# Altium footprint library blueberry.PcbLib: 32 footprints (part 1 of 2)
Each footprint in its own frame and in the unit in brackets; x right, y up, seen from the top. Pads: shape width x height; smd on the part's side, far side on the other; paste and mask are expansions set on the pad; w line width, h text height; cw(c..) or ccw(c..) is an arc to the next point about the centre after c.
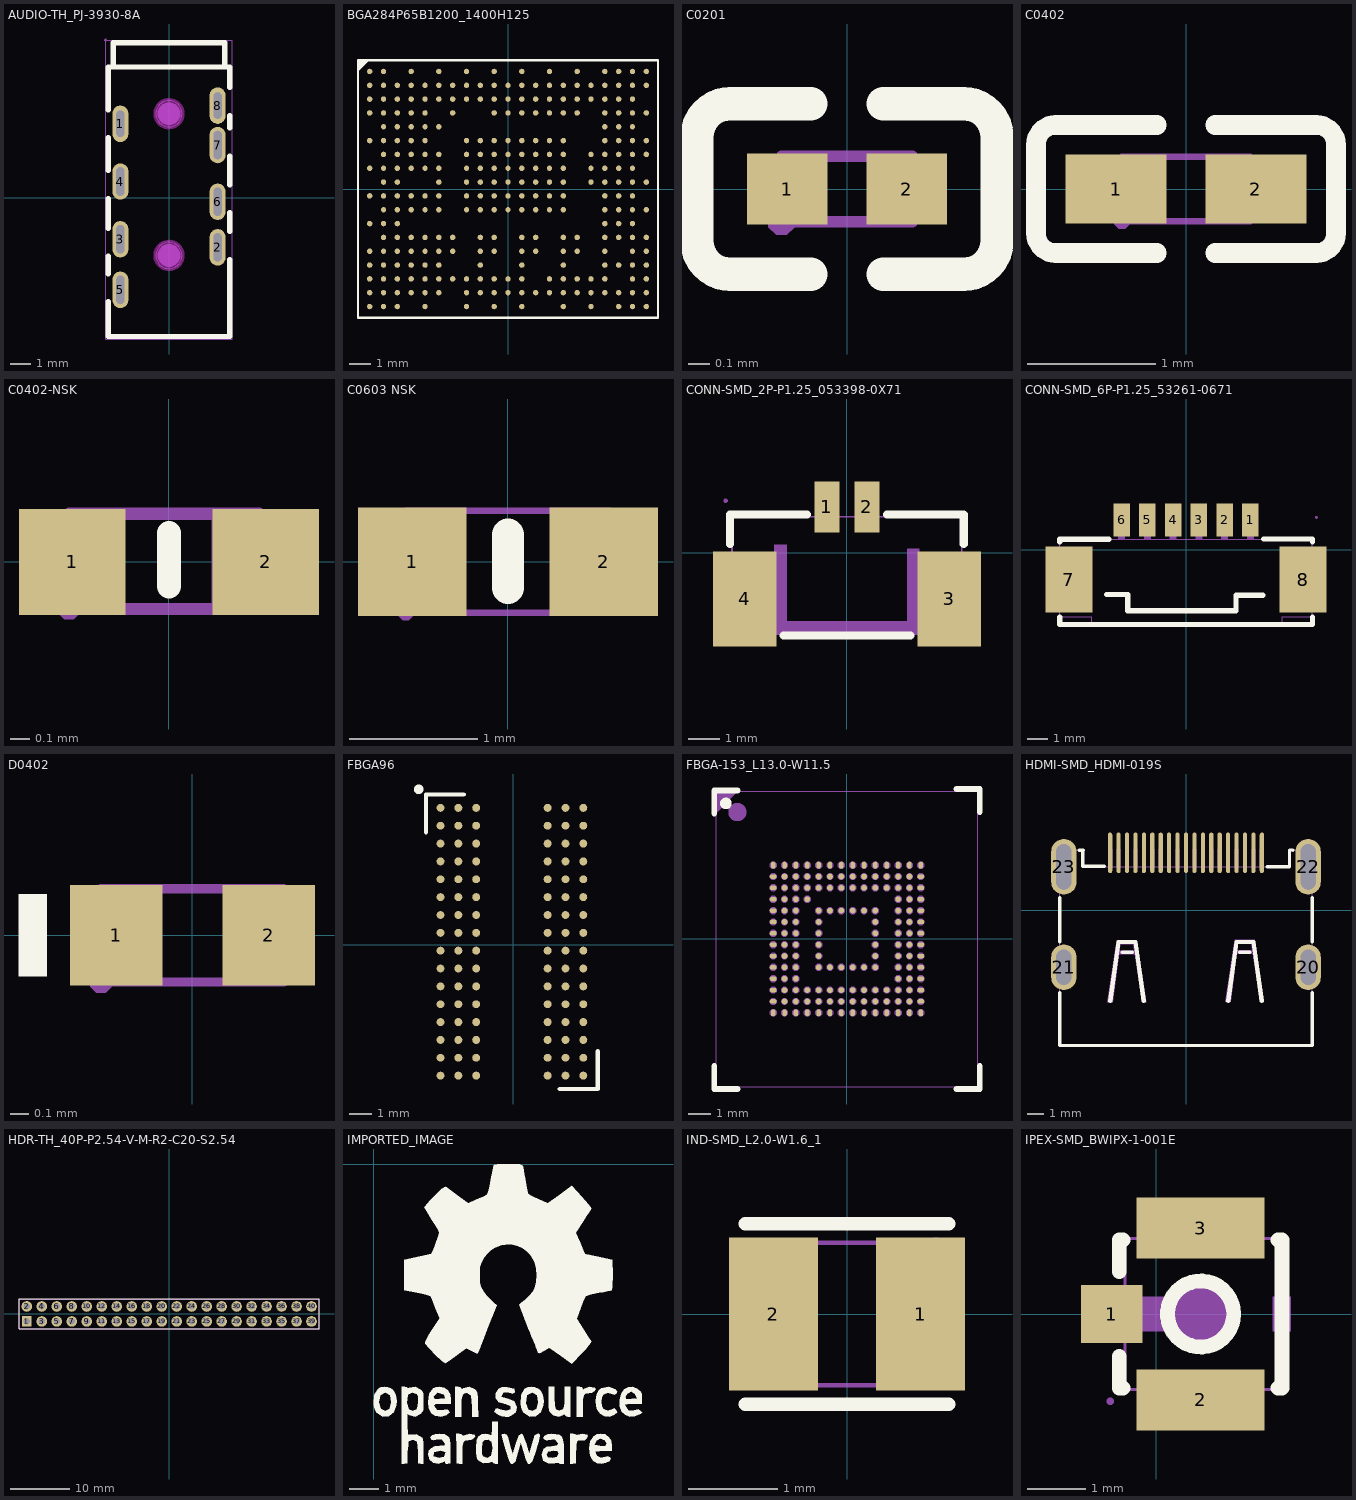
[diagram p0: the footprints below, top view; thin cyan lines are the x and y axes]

## AUDIO-TH_PJ-3930-8A [mil]
pads (8):
  oval 31.5x70.9 hole 15.7 slot 51.2 at 90 deg paste-99999 mask+2: 1(-94.5,143.7) 8(94.5,179.1)
  oval 31.5x70.9 hole 15.7 slot 55.1 at 90 deg paste-99999 mask+2: 2(94.5,-96.5) 3(-94.5,-80.7) 4(-94.5,31.5) 5(-94.5,-179.1) 6(94.5,-7.9) 7(94.5,102.4)
Top Overlay:
  lines w10: -118.1,-202.4 -118.1,-269.7 118.1,-269.7 118.1,-119.8 ; -118.1,-148 -118.1,-113.9 ; -118.1,-59.5 -118.1,-1.6 ; -118.1,52.8 -118.1,116.5 ; -118.1,170.9 -118.1,253.9 90,253.9 118.1,253.9 118.1,214.2 ; -108.3,253.9 -108.3,301.2 108.3,301.2 108.3,253.9 ; 118.1,-65.4 118.1,-29.2 ; 118.1,25.2 118.1,81 ; 118.1,135.4 118.1,159.8
Keep-Out Layer:
  board cut-out: -25.6,-112.2 -25.6,-115.57 -23.86,-122.08 -20.49,-127.92 -15.72,-132.69 -9.88,-136.06 -3.37,-137.8 3.37,-137.8 9.88,-136.06 15.72,-132.69 20.48,-127.92 23.86,-122.08 25.6,-115.57 25.6,-112.2 25.6,-108.83 23.86,-102.32 20.48,-96.48 15.72,-91.72 9.88,-88.34 3.37,-86.6 -3.37,-86.6 -9.88,-88.34 -15.72,-91.72 -20.49,-96.48 -23.86,-102.32 -25.6,-108.83
  board cut-out: -25.6,163.3 -25.6,159.93 -23.86,153.42 -20.49,147.58 -15.72,142.81 -9.88,139.44 -3.37,137.7 3.37,137.7 9.88,139.44 15.72,142.81 20.48,147.58 23.86,153.42 25.6,159.93 25.6,163.3 25.6,166.67 23.86,173.18 20.48,179.02 15.72,183.78 9.88,187.16 3.37,188.9 -3.37,188.9 -9.88,187.16 -15.72,183.78 -20.49,179.02 -23.86,173.18 -25.6,166.67
Keep-Out Layer:
  circle w10: c0,-112.2 r25.6
  circle w0.2: c0,-112.2 r25.6
  circle w10: c0,163.3 r25.6
  circle w0.2: c0,163.3 r25.6
Mechanical 1:
  circle w0.2: c0,-112.2 r25.6
  circle w0.2: c0,163.3 r25.6
Mechanical 15:
  region: 88.2,161.4 88.2,196.8 100.8,196.8 100.8,161.4
  region: 88.2,82.7 88.2,122.1 100.8,122.1 100.8,82.7
  region: 88.2,-27.6 88.2,11.8 100.8,11.8 100.8,-27.6
  region: -100.8,-198.9 -100.8,-159.5 -88.2,-159.5 -88.2,-198.9
  region: -100.8,11.8 -100.8,51.1 -88.2,51.1 -88.2,11.8
  region: -100.8,-100.3 -100.8,-61 -88.2,-61 -88.2,-100.3
  region: 88.2,-116.1 88.2,-76.7 100.8,-76.7 100.8,-116.1
  region: -100.8,126 -100.8,161.4 -88.2,161.4 -88.2,126
  region: -125.5,306.2 -125.5,305.21 -124.09,303.8 -122.11,303.8 -120.7,305.21 -120.7,306.2 -120.7,307.19 -122.11,308.6 -124.09,308.6 -125.5,307.19 -125.5,306.2
  region: -21.7,-112.2 -21.7,-116.52 -18.4,-124.49 -12.29,-130.6 -4.32,-133.9 4.32,-133.9 12.29,-130.6 18.4,-124.49 21.7,-116.52 21.7,-112.2 21.7,-107.88 18.4,-99.91 12.29,-93.8 4.32,-90.5 -4.32,-90.5 -12.29,-93.8 -18.4,-99.91 -21.7,-107.88 -21.7,-112.2
  region: -21.7,163.3 -21.7,158.98 -18.4,151.01 -12.29,144.9 -4.32,141.6 4.32,141.6 12.29,144.9 18.4,151.01 21.7,158.98 21.7,163.3 21.7,167.62 18.4,175.59 12.29,181.7 4.32,185 -4.32,185 -12.29,181.7 -18.4,175.59 -21.7,167.62 -21.7,163.3
  lines w2: -123.1,-274.7 -123.1,306.2 123.1,306.2 123.1,-274.7 -123.1,-274.7
3D body "13lB-AUDIO1-AUDIO-TH_PJ-3930-8A.step": height 214.55, standoff -118.1, extent -118.49,-275.55 118.1,303.15

## BGA284P65B1200_1400H125 [mil]
pads (284):
  round 10 smd paste+0.98 mask+1.97: A1(-255.91,217.52) A2(-230.31,217.52) A4(-179.13,217.52) A6(-127.95,217.52) A8(-76.77,217.52) A10(-25.59,217.52) A12(25.59,217.52) A14(76.77,217.52) A16(127.95,217.52) A18(179.13,217.52) A19(204.72,217.52) A20(230.31,217.52) A21(255.91,217.52) B1(-255.91,191.93) B2(-230.31,191.93) B3(-204.72,191.93) B4(-179.13,191.93) B5(-153.54,191.93) B6(-127.95,191.93) B7(-102.36,191.93) B8(-76.77,191.93) B9(-51.18,191.93) B10(-25.59,191.93) B11(0,191.93) B12(25.59,191.93) B13(51.18,191.93) B14(76.77,191.93) B15(102.36,191.93) B16(127.95,191.93) B17(153.54,191.93) B18(179.13,191.93) B19(204.72,191.93) B20(230.31,191.93) B21(255.91,191.93) C1(-255.91,166.34) C2(-230.31,166.34) C3(-204.72,166.34) C4(-179.13,166.34) C5(-153.54,166.34) C6(-127.95,166.34) C7(-102.36,166.34) C8(-76.77,166.34) C9(-51.18,166.34) C10(-25.59,166.34) C11(0,166.34) C12(25.59,166.34) C13(51.18,166.34) C14(76.77,166.34) C15(102.36,166.34) C16(127.95,166.34) C17(153.54,166.34) C18(179.13,166.34) C19(204.72,166.34) C20(230.31,166.34) D1(-255.91,140.75) D2(-230.31,140.75) D3(-204.72,140.75) D4(-179.13,140.75) D5(-153.54,140.75) D7(-102.36,140.75) D10(-25.59,140.75) D11(0,140.75) D12(25.59,140.75) D13(51.18,140.75) D14(76.77,140.75) D15(102.36,140.75) D16(127.95,140.75) D18(179.13,140.75) D19(204.72,140.75) D20(230.31,140.75) D21(255.91,140.75) E2(-230.31,115.16) E3(-204.72,115.16) E4(-179.13,115.16) E5(-153.54,115.16) E6(-127.95,115.16) E18(179.13,115.16) E19(204.72,115.16) E20(230.31,115.16) F1(-255.91,89.57) F2(-230.31,89.57) F3(-204.72,89.57) F4(-179.13,89.57) F5(-153.54,89.57) F8(-76.77,89.57) F9(-51.18,89.57) F10(-25.59,89.57) F11(0,89.57) F12(25.59,89.57) F13(51.18,89.57) F14(76.77,89.57) F15(102.36,89.57) F18(179.13,89.57) F19(204.72,89.57) F20(230.31,89.57) F21(255.91,89.57) G2(-230.31,63.98) G3(-204.72,63.98) G4(-179.13,63.98) G5(-153.54,63.98) G6(-127.95,63.98) G8(-76.77,63.98) G9(-51.18,63.98) G10(-25.59,63.98) G11(0,63.98) G12(25.59,63.98) G13(51.18,63.98) G14(76.77,63.98) G15(102.36,63.98) G17(153.54,63.98) G18(179.13,63.98) G19(204.72,63.98) G20(230.31,63.98) G21(255.91,63.98) H1(-255.91,38.39) H2(-230.31,38.39) H3(-204.72,38.39) H4(-179.13,38.39) H5(-153.54,38.39) H6(-127.95,38.39) H8(-76.77,38.39) H9(-51.18,38.39) H10(-25.59,38.39) H11(0,38.39) H12(25.59,38.39) H13(51.18,38.39) H14(76.77,38.39) H15(102.36,38.39) H17(153.54,38.39) H18(179.13,38.39) H19(204.72,38.39) H20(230.31,38.39) J2(-230.31,12.8) J3(-204.72,12.8) J6(-127.95,12.8) J8(-76.77,12.8) J9(-51.18,12.8) J10(-25.59,12.8) J11(0,12.8) J12(25.59,12.8) J13(51.18,12.8) J14(76.77,12.8) J15(102.36,12.8) J17(153.54,12.8) J18(179.13,12.8) J19(204.72,12.8) J20(230.31,12.8) J21(255.91,12.8) K1(-255.91,-12.8) K2(-230.31,-12.8) K3(-204.72,-12.8) K4(-179.13,-12.8) K5(-153.54,-12.8) K6(-127.95,-12.8) K8(-76.77,-12.8) K9(-51.18,-12.8) K10(-25.59,-12.8) K11(0,-12.8) K12(25.59,-12.8) K13(51.18,-12.8) K14(76.77,-12.8) K15(102.36,-12.8) K18(179.13,-12.8) K19(204.72,-12.8) K20(230.31,-12.8) L2(-230.31,-38.39) L3(-204.72,-38.39) L4(-179.13,-38.39) L5(-153.54,-38.39) L6(-127.95,-38.39) L8(-76.77,-38.39) L9(-51.18,-38.39) L10(-25.59,-38.39) L11(0,-38.39) L12(25.59,-38.39) L13(51.18,-38.39) L14(76.77,-38.39) L15(102.36,-38.39) L18(179.13,-38.39) L19(204.72,-38.39) L20(230.31,-38.39) L21(255.91,-38.39) M1(-255.91,-63.98) M2(-230.31,-63.98) M3(-204.72,-63.98) M18(179.13,-63.98) M19(204.72,-63.98) M20(230.31,-63.98) N2(-230.31,-89.57) N3(-204.72,-89.57) N4(-179.13,-89.57) N5(-153.54,-89.57) N6(-127.95,-89.57) N7(-102.36,-89.57) N9(-51.18,-89.57) N10(-25.59,-89.57) N12(25.59,-89.57) N13(51.18,-89.57) N15(102.36,-89.57) N16(127.95,-89.57) N18(179.13,-89.57) N19(204.72,-89.57) N20(230.31,-89.57) N21(255.91,-89.57) P1(-255.91,-115.16) P2(-230.31,-115.16) P3(-204.72,-115.16) P4(-179.13,-115.16) P5(-153.54,-115.16) P6(-127.95,-115.16) P7(-102.36,-115.16) P9(-51.18,-115.16) P10(-25.59,-115.16) P12(25.59,-115.16) P13(51.18,-115.16) P15(102.36,-115.16) P16(127.95,-115.16) P18(179.13,-115.16) P20(230.31,-115.16) P21(255.91,-115.16) R1(-255.91,-140.75) R2(-230.31,-140.75) R3(-204.72,-140.75) R4(-179.13,-140.75) R5(-153.54,-140.75) R6(-127.95,-140.75) R9(-51.18,-140.75) R12(25.59,-140.75) R15(102.36,-140.75) R18(179.13,-140.75) R19(204.72,-140.75) R20(230.31,-140.75) R21(255.91,-140.75) T1(-255.91,-166.34) T2(-230.31,-166.34) T3(-204.72,-166.34) T4(-179.13,-166.34) T5(-153.54,-166.34) T6(-127.95,-166.34) T7(-102.36,-166.34) T8(-76.77,-166.34) T9(-51.18,-166.34) T10(-25.59,-166.34) T11(0,-166.34) T12(25.59,-166.34) T14(76.77,-166.34) T15(102.36,-166.34) T16(127.95,-166.34) T17(153.54,-166.34) T18(179.13,-166.34) T20(230.31,-166.34) T21(255.91,-166.34) U1(-255.91,-191.93) U2(-230.31,-191.93) U3(-204.72,-191.93) U4(-179.13,-191.93) U5(-153.54,-191.93) U6(-127.95,-191.93) U8(-76.77,-191.93) U9(-51.18,-191.93) U10(-25.59,-191.93) U11(0,-191.93) U12(25.59,-191.93) U13(51.18,-191.93) U14(76.77,-191.93) U15(102.36,-191.93) U16(127.95,-191.93) U17(153.54,-191.93) U18(179.13,-191.93) U19(204.72,-191.93) U20(230.31,-191.93) U21(255.91,-191.93) V1(-255.91,-217.52) V2(-230.31,-217.52) V3(-204.72,-217.52) V5(-153.54,-217.52) V8(-76.77,-217.52) V10(-25.59,-217.52) V12(25.59,-217.52) V15(102.36,-217.52) V17(153.54,-217.52) V19(204.72,-217.52) V20(230.31,-217.52) V21(255.91,-217.52)
Top Overlay:
  region: -277.56,238.19 -256.81,238.19 -277.56,217.44
  lines w3.94: -277.56,-238.19 -277.56,238.19 277.56,238.19 277.56,-238.19 -277.56,-238.19
Mechanical 1:
  lines w1: 276.77,-238.19 -277.56,-238.19 ; -277.56,-238.19 277.56,-238.19 277.56,238.19 ; -277.56,-238.19 -277.56,238.19 ; -277.56,-238.19 -277.56,238.19 ; -277.56,238.19 277.56,238.19 ; -277.56,238.19 277.56,238.19
3D body "13lB-U2-BGA284P65B1200_1400H125.step": height 55.6, standoff 0.09, extent -272,-234 272,234

## C0201 [mil]
pads (2):
  rect 14.51x12.76 smd paste-3937.01 mask+2: 1(-10.8,0) 2(10.8,0)
Top Overlay:
  lines w6: -6.54,-15.38 -21.05,-15.38 cw(c-21.05,-9.38) -27.05,-9.38 -27.05,9.38 cw(c-21.05,9.38) -21.05,15.38 -6.54,15.38 ; 6.54,-15.38 21.05,-15.38 ccw(c21.05,-9.38) 27.05,-9.38 27.05,9.38 ccw(c21.05,9.38) 21.05,15.38 6.54,15.38
Top Paste:
  region: -3.19,-5.43 -3.19,5.43 -4.13,6.38 -17.1,6.38 -18.05,5.43 -18.05,-5.43 -17.1,-6.38 -4.13,-6.38
  region: 3.19,-5.43 3.19,5.43 4.13,6.38 17.1,6.38 18.05,5.43 18.05,-5.43 17.1,-6.38 4.13,-6.38
Mechanical 15:
  region: -11.81,-8.27 -10.83,-8.27 -9.45,-6.89 -9.45,-4.93 -10.83,-3.55 -11.81,-3.55 -12.79,-3.55 -14.17,-4.93 -14.17,-6.89 -12.79,-8.27 -11.81,-8.27
  region: 11.81,-5.91 11.81,5.91 5.91,5.91 5.91,-5.91
  region: -11.81,-5.91 -11.81,5.91 -5.91,5.91 -5.91,-5.91
  lines w2: -11.81,-5.91 11.81,-5.91 11.81,5.91 -11.81,5.91 -11.81,-5.91
3D body "13lB-C107-C0201.step": height 12.01, standoff 0, extent -11.81,-5.91 11.81,5.91

## C0402 [mm]
pads (2):
  rect 0.79x0.54 smd paste-100 mask+0.051: 1(-0.545,0) 2(0.545,0)
Top Overlay:
  lines w0.152: -0.226,-0.499 -1.016,-0.499 cw(c-1.016,-0.346) -1.169,-0.346 -1.169,0.346 cw(c-1.016,0.346) -1.016,0.499 -0.226,0.499 ; 0.226,-0.499 1.016,-0.499 ccw(c1.016,-0.346) 1.169,-0.346 1.169,0.346 ccw(c1.016,0.346) 1.016,0.499 0.226,0.499
Top Paste:
  region: 0.78,0.225 0.78,-0.225 0.73,-0.275 0.25,-0.275 0.18,-0.225 0.18,0.225 0.25,0.275 0.73,0.275
  region: -0.18,0.225 -0.18,-0.225 -0.25,-0.275 -0.73,-0.275 -0.78,-0.225 -0.78,0.225 -0.73,0.275 -0.25,0.275
Mechanical 15:
  region: 0.5,-0.25 0.5,0.25 0.25,0.25 0.25,-0.25
  region: -0.5,-0.25 -0.5,0.25 -0.25,0.25 -0.25,-0.25
  region: -0.5,-0.31 -0.475,-0.31 -0.44,-0.275 -0.44,-0.225 -0.475,-0.19 -0.5,-0.19 -0.525,-0.19 -0.56,-0.225 -0.56,-0.275 -0.525,-0.31 -0.5,-0.31
  lines w0.051: -0.5,-0.25 0.5,-0.25 0.5,0.25 -0.5,0.25 -0.5,-0.25
3D body "13lB-C87-C0402.step": height 0.5, standoff 0, extent -0.5,-0.25 0.5,0.25

## C0402-NSK [mil]
pads (2):
  rect 22x22 smd paste+0 mask+2: 1(-20,0) 2(20,0)
Top Overlay:
  lines w5: 0,-5 0,6
Mechanical 15:
  region: -23.03,-9.47 -23.03,-8.49 -21.64,-7.11 -19.68,-7.11 -18.3,-8.49 -18.3,-9.47 -18.3,-10.45 -19.68,-11.83 -21.64,-11.83 -23.03,-10.45 -23.03,-9.47
  region: 18.7,-9.47 18.7,10.21 8.86,10.21 8.86,-9.47
  region: -20.67,-9.47 -20.67,10.21 -10.83,10.21 -10.83,-9.47
  lines w2: -20.67,-9.47 -20.67,10.21 18.7,10.21 18.7,-9.47 -20.67,-9.47 ; -20,-10 -20,9.69 19.37,9.69 19.37,-10 -20,-10
3D body "13lB-C58-C0402-NSK.step": height 19.7, standoff 0, extent -19.7,-9.85 19.7,9.85

## C0603 NSK [mm]
pads (2):
  rect 0.85x0.85 smd paste+0 mask+0.051: 1(-0.75,0) 2(0.75,0)
Top Overlay:
  lines w0.254: 0,-0.205 0,0.21
Mechanical 15:
  region: -0.8,-0.46 -0.776,-0.459 -0.742,-0.424 -0.742,-0.376 -0.776,-0.341 -0.8,-0.34 -0.825,-0.341 -0.859,-0.376 -0.859,-0.425 -0.825,-0.459 -0.8,-0.46
  region: -0.8,-0.4 -0.8,0.4 -0.5,0.4 -0.5,-0.4
  region: 0.8,-0.4 0.8,0.4 0.5,0.4 0.5,-0.4
  lines w0.051: -0.8,-0.4 -0.8,0.4 0.8,0.4 0.8,-0.4 -0.8,-0.4
3D body "13lB-C4-C0603 NSK.step": height 0.8, standoff 0, extent -0.8,-0.4 0.8,0.4

## CONN-SMD_2P-P1.25_053398-0X71 [mil]
pads (4):
  rect 31.5x63 smd paste+0 mask+2: 1(-24.8,57.1) 2(24.8,57.1)
  rect 78.7x118.1 smd paste+0 mask+2: 3(127.2,-57.1) 4(-127.1,-57.1)
Top Overlay:
  lines w10: -145,11.1 -145,47.7 -49.6,47.7 ; -78.7,-102.4 78.7,-102.4 ; 49.6,47.6 145,47.6 145,11.1
Mechanical 6:
  region: -90,10 -75,10 -75,-85 75,-85 75,5 90,5 90,-100 -90,-100
Mechanical 15:
  region: -153,64.8 -153,63.81 -151.59,62.4 -149.61,62.4 -148.2,63.81 -148.2,64.8 -148.2,65.79 -149.61,67.2 -151.59,67.2 -153,65.79 -153,64.8
  region: 31.1,64.8 31.1,39.2 18.5,39.2 18.5,64.8
  region: -18.5,64.8 -18.5,39.2 -31.1,39.2 -31.1,64.8
  region: 150.6,-13.8 150.6,-100.4 91.5,-100.4 91.5,-13.8
  region: -91.5,-13.8 -91.5,-100.4 -150.6,-100.4 -150.6,-13.8
  lines w2: -142.7,-100.6 -142.7,45.1 142.7,45.1 142.7,-100.6 -142.7,-100.6
3D body "13lB-FAN1-CONN-SMD_2P-P1.25_053398-0X71.step": height 184.97, standoff 0, extent -150.54,-97.4 150.54,64

## CONN-SMD_6P-P1.25_53261-0671 [mil]
pads (8):
  rect 31.5x63 smd paste+0 mask+2: 1(123,57.1) 2(73.8,57.1) 3(24.6,57.1) 4(-24.6,57.1) 5(-73.8,57.1) 6(-123,57.1)
  rect 90.6x126 smd paste+0 mask+2: 7(-223.4,-57.1) 8(223.4,-57.1)
Top Overlay:
  lines w10: -240.9,-129.2 -240.9,-142.9 241.7,-142.9 241.7,-129.2 ; -240.9,15 -240.9,20.1 -147.6,20.1 ; -151.2,-85.8 -111.4,-85.8 -111.4,-116.5 95.3,-116.5 95.3,-87 147.2,-87 ; 148.4,20.5 240.6,20.5 ; 241.7,15 241.7,20.5
Mechanical 15:
  region: 249,-19.1 249,-105.7 190.7,-105.7 190.7,-19.1
  region: -190.7,-19.1 -190.7,-105.7 -249,-105.7 -249,-19.1
  region: 129.3,44.8 129.3,19.7 116.7,19.7 116.7,44.8
  region: 80.1,44.8 80.1,19.7 67.5,19.7 67.5,44.8
  region: 30.9,44.8 30.9,19.7 18.3,19.7 18.3,44.8
  region: -18.3,44.8 -18.3,19.7 -30.9,19.7 -30.9,44.8
  region: -67.5,44.8 -67.5,19.7 -80.1,19.7 -80.1,44.8
  region: -116.7,44.8 -116.7,19.7 -129.3,19.7 -129.3,44.8
  region: 129.3,61.5 129.3,43.8 116.7,43.8 116.7,61.5
  region: 80.1,61.5 80.1,43.8 67.5,43.8 67.5,61.5
  region: 30.9,61.5 30.9,43.8 18.3,43.8 18.3,61.5
  region: -18.3,61.5 -18.3,43.8 -30.9,43.8 -30.9,61.5
  region: -67.5,61.5 -67.5,43.8 -80.1,43.8 -80.1,61.5
  region: -116.7,61.5 -116.7,43.8 -129.3,43.8 -129.3,61.5
  region: 249,59.1 249.97,59.13 251.32,60.53 251.32,62.47 249.97,63.87 249,63.9 248.03,63.87 246.68,62.47 246.68,60.53 248.03,59.13 249,59.1
  lines w2: -241.1,-127.6 -241.1,20.3 241.1,20.3 241.1,-127.6 184.1,-127.6 184.1,-143.3 -180.1,-143.3 -180.1,-127.6 -241.1,-127.6
3D body "13lB-CN1-CONN-SMD_6P-P1.25_53261-0671.step": height 133.88, standoff 0, extent -248.78,-142.95 249.18,61.35

## D0402 [mil]
pads (2):
  rect 19.89x21.68 smd paste-3937.01 mask+2: 1(-16.4,0) 2(16.4,0)
Top Overlay:
  region: -31.35,-8.85 -31.35,8.84 -37.35,8.84 -37.35,-8.85
Top Paste:
  region: -5.81,9.24 -5.81,-9.24 -7.42,-10.84 -24.74,-10.84 -26.35,-9.24 -26.35,9.24 -24.74,10.84 -7.42,10.84
  region: 5.81,9.24 5.81,-9.24 7.42,-10.84 24.74,-10.84 26.35,-9.24 26.35,9.24 24.74,10.84 7.42,10.84
Mechanical 6:
  region: -17.28,-1.21 -17.28,1.2 -7.64,1.2 -7.64,-1.21
  region: 17.27,-1.21 17.27,1.2 7.64,1.2 7.64,-1.21
  region: 13.66,-8.03 13.66,8.03 11.25,8.03 11.25,-8.03
Mechanical 15:
  region: -22.05,-10.04 -22.05,-9.06 -20.67,-7.68 -18.71,-7.68 -17.33,-9.06 -17.33,-10.04 -17.33,-11.02 -18.71,-12.4 -20.67,-12.4 -22.05,-11.02 -22.05,-10.04
  region: -19.69,-10.04 -19.69,10.04 -10.24,10.04 -10.24,-10.04
  region: 19.68,-10.04 19.68,10.04 10.23,10.04 10.23,-10.04
  lines w2: -19.69,-10.04 -19.69,10.04 19.68,10.04 19.68,-10.04 -19.69,-10.04
3D body "13lB-D3-D0402.step": height 13.82, standoff 0, extent -19.69,-9.85 19.68,9.84

## FBGA96 [mil]
pads (96):
  round 14 smd: A1(-128.4,241.4) A2(-96.9,241.4) A3(-65.4,241.4) A7(60.6,241.4) A8(92.1,241.4) A9(123.6,241.4) B1(-128.4,209.9) B2(-96.9,209.9) B3(-65.4,209.9) B7(60.6,209.9) B8(92.1,209.9) B9(123.6,209.9) C1(-128.4,178.4) C2(-96.9,178.4) C3(-65.4,178.4) C7(60.6,178.4) C8(92.1,178.4) C9(123.6,178.4) D1(-128.4,146.9) D2(-96.9,146.9) D3(-65.4,146.9) D7(60.6,146.9) D8(92.1,146.9) D9(123.6,146.9) E1(-128.4,115.4) E2(-96.9,115.4) E3(-65.4,115.4) E7(60.6,115.4) E8(92.1,115.4) E9(123.6,115.4) F1(-128.4,83.9) F2(-96.9,83.9) F3(-65.4,83.9) F7(60.6,83.9) F8(92.1,83.9) F9(123.6,83.9) G1(-128.4,52.4) G2(-96.9,52.4) G3(-65.4,52.4) G7(60.6,52.4) G8(92.1,52.4) G9(123.6,52.4) H1(-128.4,20.9) H2(-96.9,20.9) H3(-65.4,20.9) H7(60.6,20.9) H8(92.1,20.9) H9(123.6,20.9) J1(-128.4,-10.6) J2(-96.9,-10.6) J3(-65.4,-10.6) J7(60.6,-10.6) J8(92.1,-10.6) J9(123.6,-10.6) K1(-128.4,-42.1) K2(-96.9,-42.1) K3(-65.4,-42.1) K7(60.6,-42.1) K8(92.1,-42.1) K9(123.6,-42.1) L1(-128.4,-73.6) L2(-96.9,-73.6) L3(-65.4,-73.6) L7(60.6,-73.6) L8(92.1,-73.6) L9(123.6,-73.6) M1(-128.4,-105.1) M2(-96.9,-105.1) M3(-65.4,-105.1) M7(60.6,-105.1) M8(92.1,-105.1) M9(123.6,-105.1) N1(-128.4,-136.6) N2(-96.9,-136.6) N3(-65.4,-136.6) N7(60.6,-136.6) N8(92.1,-136.6) N9(123.6,-136.6) P1(-128.4,-168.1) P2(-96.9,-168.1) P3(-65.4,-168.1) P7(60.6,-168.1) P8(92.1,-168.1) P9(123.6,-168.1) R1(-128.4,-199.6) R2(-96.9,-199.6) R3(-65.4,-199.6) R7(60.6,-199.6) R8(92.1,-199.6) R9(123.6,-199.6) T1(-128.4,-231.1) T2(-96.9,-231.1) T3(-65.4,-231.1) T7(60.6,-231.1) T8(92.1,-231.1) T9(123.6,-231.1)
Top Overlay:
  lines w7.9: -154,198 -154,265 -87.1,265 ; 82.2,-254.7 149.1,-254.7 149.1,-187.8
  lines w15.7: -167.69,273.91 ccw(c-167,274) -166.31,274 ccw(c-167,274) -167.69,274.1
3D body "13lB-U3-FBGA96.step": height 46, standoff 0.15, extent -186.5,-290.11 186.5,290.11

## FBGA-153_L13.0-W11.5 [mm]
pads (153):
  oval 0.2x0.305 smd paste-100 mask+0.051: A1(-3.25,3.25) A2(-2.75,3.25) A3(-2.25,3.25) A4(-1.75,3.25) A5(-1.25,3.25) A6(-0.75,3.25) A7(-0.25,3.25) A8(0.25,3.25) A9(0.75,3.25) A10(1.25,3.25) A11(1.75,3.25) A12(2.25,3.25) A13(2.75,3.25) A14(3.25,3.25) P1(-3.25,-3.25) P2(-2.75,-3.25) P3(-2.25,-3.25) P4(-1.75,-3.25) P5(-1.25,-3.25) P6(-0.75,-3.25) P7(-0.25,-3.25) P8(0.25,-3.25) P9(0.75,-3.25) P10(1.25,-3.25) P11(1.75,-3.25) P12(2.25,-3.25) P13(2.75,-3.25) P14(3.25,-3.25)
  oval 0.305x0.2 smd paste-100 mask+0.051: B1(-3.25,2.75) B14(3.25,2.75) C1(-3.25,2.25) C14(3.25,2.25) D1(-3.25,1.75) D14(3.25,1.75) E1(-3.25,1.25) E14(3.25,1.25) F1(-3.25,0.75) F14(3.25,0.75) G1(-3.25,0.25) G14(3.25,0.25) H1(-3.25,-0.25) H14(3.25,-0.25) J1(-3.25,-0.75) J14(3.25,-0.75) K1(-3.25,-1.25) K14(3.25,-1.25) L1(-3.25,-1.75) L14(3.25,-1.75) M1(-3.25,-2.25) M14(3.25,-2.25) N1(-3.25,-2.75) N14(3.25,-2.75)
  round 0.25 smd paste-100 mask+0.051: B2(-2.75,2.75) B3(-2.25,2.75) B4(-1.75,2.75) B5(-1.25,2.75) B6(-0.75,2.75) B7(-0.25,2.75) B8(0.25,2.75) B9(0.75,2.75) B10(1.25,2.75) B11(1.75,2.75) B12(2.25,2.75) B13(2.75,2.75) C2(-2.75,2.25) C3(-2.25,2.25) C4(-1.75,2.25) C5(-1.25,2.25) C6(-0.75,2.25) C7(-0.25,2.25) C8(0.25,2.25) C9(0.75,2.25) C10(1.25,2.25) C11(1.75,2.25) C12(2.25,2.25) C13(2.75,2.25) D2(-2.75,1.75) D3(-2.25,1.75) D4(-1.75,1.75) D12(2.25,1.75) D13(2.75,1.75) E2(-2.75,1.25) E3(-2.25,1.25) E5(-1.25,1.25) E6(-0.75,1.25) E7(-0.25,1.25) E8(0.25,1.25) E9(0.75,1.25) E10(1.25,1.25) E12(2.25,1.25) E13(2.75,1.25) F2(-2.75,0.75) F3(-2.25,0.75) F5(-1.25,0.75) F10(1.25,0.75) F12(2.25,0.75) F13(2.75,0.75) G2(-2.75,0.25) G3(-2.25,0.25) G5(-1.25,0.25) G10(1.25,0.25) G12(2.25,0.25) G13(2.75,0.25) H2(-2.75,-0.25) H3(-2.25,-0.25) H5(-1.25,-0.25) H10(1.25,-0.25) H12(2.25,-0.25) H13(2.75,-0.25) J2(-2.75,-0.75) J3(-2.25,-0.75) J5(-1.25,-0.75) J10(1.25,-0.75) J12(2.25,-0.75) J13(2.75,-0.75) K2(-2.75,-1.25) K3(-2.25,-1.25) K5(-1.25,-1.25) K6(-0.75,-1.25) K7(-0.25,-1.25) K8(0.25,-1.25) K9(0.75,-1.25) K10(1.25,-1.25) K12(2.25,-1.25) K13(2.75,-1.25) L2(-2.75,-1.75) L3(-2.25,-1.75) L12(2.25,-1.75) L13(2.75,-1.75) M2(-2.75,-2.25) M3(-2.25,-2.25) M4(-1.75,-2.25) M5(-1.25,-2.25) M6(-0.75,-2.25) M7(-0.25,-2.25) M8(0.25,-2.25) M9(0.75,-2.25) M10(1.25,-2.25) M11(1.75,-2.25) M12(2.25,-2.25) M13(2.75,-2.25) N2(-2.75,-2.75) N3(-2.25,-2.75) N4(-1.75,-2.75) N5(-1.25,-2.75) N6(-0.75,-2.75) N7(-0.25,-2.75) N8(0.25,-2.75) N9(0.75,-2.75) N10(1.25,-2.75) N11(1.75,-2.75) N12(2.25,-2.75) N13(2.75,-2.75)
Top Overlay:
  circle w0.254: c-5.334,5.969 r0.127
  lines w0.254: -5.841,-5.587 -5.843,-6.605 -4.825,-6.603 ; -5.841,5.524 -5.842,6.541 -4.825,6.54 ; 4.826,-6.604 5.843,-6.605 5.842,-5.588 ; 4.825,6.603 5.843,6.605 5.841,5.587
Top Paste:
  drawing of 153 lines, arcs and shapes, not listed
Mechanical 6:
  circle w0.4: c-4.826,5.588 r0.2
  region: -4.826,6.477 -5.715,6.477 -5.715,5.588
Mechanical 15:
  drawing of 158 lines, arcs and shapes, not listed
3D body "13lB-U4-FBGA-153_L13.0-W11.5.step": height 0.92, standoff 0, extent -5.785,-6.54 5.785,6.54

## HDMI-SMD_HDMI-019S [mm]
pads (23):
  oval 0.25x2.4 smd paste-100 mask+0.051: 1(4.501,3.396) 2(4.001,3.396) 3(3.501,3.396) 4(3.001,3.396) 5(2.5,3.396) 6(2,3.396) 7(1.5,3.396) 8(1,3.396) 9(0.5,3.396) 10(0,3.396) 11(-0.5,3.396) 12(-1,3.396) 13(-1.5,3.396) 14(-2,3.396) 15(-2.5,3.396) 16(-3.001,3.396) 17(-3.501,3.396) 18(-4.001,3.396) 19(-4.501,3.396)
  oval 1.5x2.7 hole 0.9 slot 2.1 at 90 deg copper offset -0.001,0.001 paste-2539.97 mask+0.051: 20(7.251,-3.397)
  oval 1.5x2.7 hole 0.9 slot 2.1 at 90 deg copper offset 0.001,0.001 paste-2539.97 mask+0.051: 21(-7.251,-3.397)
  oval 1.5x3.3 hole 0.9 slot 2.7 at 90 deg copper offset -0.001,0.001 paste-2539.97 mask+0.051: 22(7.251,2.563)
  oval 1.5x3.3 hole 0.9 slot 2.7 at 90 deg copper offset 0.001,0.001 paste-2539.97 mask+0.051: 23(-7.251,2.563)
Top Overlay:
  lines w0.2: -7.5,-4.917 -7.5,-8.036 7.5,-8.036 7.5,-4.917 ; -7.5,-1.875 -7.5,0.743 ; -6.35,3.557 -6.107,3.557 -6.107,3.545 -6.12,3.545 -6.12,2.592 -4.837,2.592 ; -3.8,-2.504 -3.2,-2.504 ; 3.2,-2.504 3.8,-2.504 ; 4.83,2.565 6.08,2.565 6.08,2.575 6.145,2.575 6.145,3.563 6.352,3.563 6.352,3.556 ; 7.5,-1.876 7.5,0.743
  lines w0.254: -4.5,-5.404 -4,-1.904 -3,-1.904 -2.5,-5.404 ; 2.5,-5.404 3,-1.904 4,-1.904 4.5,-5.404
Top Paste:
  drawing of 23 lines, arcs and shapes, not listed
Mechanical 6:
  region: 2.332,-5.448 2.642,-5.448 3.084,-2.014 3.875,-2.005 4.392,-5.457 4.627,-5.439 4.082,-1.751 2.896,-1.751
  region: 3.047,-2.381 3.884,-2.362 3.931,-2.598 3.037,-2.607
  region: -3.951,-2.419 -3.114,-2.4 -3.067,-2.636 -3.961,-2.645
  region: -4.666,-5.486 -4.356,-5.486 -3.914,-2.052 -3.123,-2.043 -2.606,-5.495 -2.371,-5.477 -2.916,-1.789 -4.102,-1.789
Mechanical 15:
  region: 4.391,3.596 4.611,3.596 4.611,2.496 4.391,2.496
  region: 7,-2.896 7.5,-2.896 7.5,-3.896 7,-3.896
  region: -7.5,-2.896 -7,-2.896 -7,-3.896 -7.5,-3.896
  region: -7.5,3.564 -7,3.564 -7,1.564 -7.5,1.564
  region: 7,3.564 7.5,3.564 7.5,1.564 7,1.564
  region: -0.11,3.596 0.11,3.596 0.11,2.496 -0.11,2.496
  region: 0.39,3.596 0.61,3.596 0.61,2.496 0.39,2.496
  region: 0.89,3.596 1.11,3.596 1.11,2.496 0.89,2.496
  region: 1.39,3.596 1.61,3.596 1.61,2.496 1.39,2.496
  region: 1.89,3.596 2.11,3.596 2.11,2.496 1.89,2.496
  region: 2.39,3.596 2.61,3.596 2.61,2.496 2.39,2.496
  region: 2.891,3.596 3.111,3.596 3.111,2.496 2.891,2.496
  region: 3.391,3.596 3.611,3.596 3.611,2.496 3.391,2.496
  region: 3.891,3.596 4.111,3.596 4.111,2.496 3.891,2.496
  region: -0.61,3.596 -0.39,3.596 -0.39,2.496 -0.61,2.496
  region: -1.11,3.596 -0.89,3.596 -0.89,2.496 -1.11,2.496
  region: -1.61,3.596 -1.39,3.596 -1.39,2.496 -1.61,2.496
  region: -2.11,3.596 -1.89,3.596 -1.89,2.496 -2.11,2.496
  region: -2.61,3.596 -2.39,3.596 -2.39,2.496 -2.61,2.496
  region: -3.111,3.596 -2.891,3.596 -2.891,2.496 -3.111,2.496
  region: -3.611,3.596 -3.391,3.596 -3.391,2.496 -3.611,2.496
  region: -4.111,3.596 -3.891,3.596 -3.891,2.496 -4.111,2.496
  region: -4.611,3.596 -4.391,3.596 -4.391,2.496 -4.611,2.496
  region: 7.56,3.596 7.56,3.621 7.525,3.655 7.476,3.655 7.441,3.621 7.44,3.596 7.441,3.572 7.476,3.537 7.525,3.537 7.56,3.572 7.56,3.596
  lines w0.051: -7.5,-8.036 -7.5,3.564 -6.1,3.564 -6.1,2.567 6.1,2.567 6.1,3.564 7.5,3.564 7.5,-8.036 -7.5,-8.036
3D body "13lB-HDMIOUT-HDMI-SMD_HDMI-019S.step": height 5.71, standoff -2.3, extent -7.5,-8.011 7.5,3.889

## HDR-TH_40P-P2.54-V-M-R2-C20-S2.54 [mm]
pads (40):
  rect 1.575x1.8 hole 1.1: 1(-24.13,-1.27)
  round 1.8 hole 1.1: 2(-24.13,1.27) 3(-21.59,-1.27) 4(-21.59,1.27) 5(-19.05,-1.27) 6(-19.05,1.27) 7(-16.51,-1.27) 8(-16.51,1.27) 9(-13.97,-1.27) 10(-13.97,1.27) 11(-11.43,-1.27) 12(-11.43,1.27) 13(-8.89,-1.27) 14(-8.89,1.27) 15(-6.35,-1.27) 16(-6.35,1.27) 17(-3.81,-1.27) 18(-3.81,1.27) 19(-1.27,-1.27) 20(-1.27,1.27) 21(1.27,-1.27) 22(1.27,1.27) 23(3.81,-1.27) 24(3.81,1.27) 25(6.35,-1.27) 26(6.35,1.27) 27(8.89,-1.27) 28(8.89,1.27) 29(11.43,-1.27) 30(11.43,1.27) 31(13.97,-1.27) 32(13.97,1.27) 33(16.51,-1.27) 34(16.51,1.27) 35(19.05,-1.27) 36(19.05,1.27) 37(21.59,-1.27) 38(21.59,1.27) 39(24.13,-1.27) 40(24.13,1.27)
Top Overlay:
  lines w0.203: -25.4,-2.54 -25.4,2.54 25.4,2.54 25.4,-2.54 -25.4,-2.54
Mechanical 15:
  drawing of 45 lines, arcs and shapes, not listed
3D body "13lB-H1-HDR-TH_40P-P2.54-V-M-R2-C20-S2.54.step": height 8.54, standoff -3, extent -25.4,-2.5 25.41,2.5

## IMPORTED_IMAGE [mil]
Top Overlay:
  drawing of 18 lines, arcs and shapes, not listed

## IND-SMD_L2.0-W1.6_1 [mm]
pads (2):
  rect 1x1.72 smd paste+0 mask+0.051: 1(0.828,0) 2(-0.828,0)
Top Overlay:
  lines w0.152: -1.143,-1.016 1.143,-1.016 ; -1.143,1.016 1.143,1.016
Mechanical 15:
  region: 1,0.74 1.025,0.74 1.06,0.775 1.06,0.825 1.025,0.86 1,0.86 0.975,0.86 0.94,0.825 0.94,0.775 0.975,0.74 1,0.74
  region: 0.4,0.8 1,0.8 1,-0.8 0.4,-0.8
  region: -1,0.8 -0.4,0.8 -0.4,-0.8 -1,-0.8
  lines w0.051: -1,-0.8 -1,0.8 1,0.8 1,-0.8 -1,-0.8
3D body "13lB-L1-IND-SMD_L2.0-W1.6_1.step": height 1.12, standoff 0, extent -1.01,-0.8 1.01,0.8

## IPEX-SMD_BWIPX-1-001E [mm]
pads (3):
  rect 1.05x1 smd: 1(-0.763,0)
  rect 2.2x1.05 smd: 2(0.763,-1.475) 3(0.763,1.475)
Top Overlay:
  circle w0.254: c0.763,0 r0.568
  lines w0.254: -0.635,-0.731 -0.635,-1.27 -0.569,-1.27 ; -0.635,0.731 -0.635,1.27 -0.569,1.27 ; 2.094,-1.27 2.16,-1.27 2.16,-0.731 2.16,0.731 2.16,1.27 2.094,1.27
Mechanical 6:
  circle w0.2: c-1.015,0 r0.1
  region: 1.293,0 1.293,-0.101 1.216,-0.288 1.073,-0.431 0.886,-0.508 0.785,-0.508 0.727,-0.507 0.613,-0.478 0.509,-0.424 0.42,-0.347 0.385,-0.3 -0.45,-0.3 -0.45,0.3 0.385,0.3 0.42,0.347 0.509,0.424 0.613,0.478 0.727,0.507 0.785,0.508 0.886,0.508 1.073,0.431 1.216,0.288 1.293,0.101 1.293,0
Mechanical 15:
  region: -0.437,0.3 -0.437,-0.3 -0.787,-0.3 -0.787,0.3
  region: 1.293,0 1.293,-0.101 1.216,-0.288 1.073,-0.431 0.886,-0.508 0.785,-0.508 0.727,-0.507 0.613,-0.478 0.509,-0.424 0.42,-0.347 0.385,-0.3 -0.45,-0.3 -0.45,0.3 0.385,0.3 0.42,0.347 0.509,0.424 0.613,0.478 0.727,0.507 0.785,0.508 0.886,0.508 1.073,0.431 1.216,0.288 1.293,0.101 1.293,0
  region: 2,0.3 2.312,0.3 2.312,-0.3 2,-0.3
  region: 1.663,-1.5 -0.137,-1.5 -0.137,-1.1 1.663,-1.1
  region: 1.663,1.1 -0.137,1.1 -0.137,1.5 1.663,1.5
  region: -0.727,-1.5 -0.728,-1.475 -0.763,-1.441 -0.812,-1.441 -0.847,-1.475 -0.847,-1.5 -0.847,-1.524 -0.812,-1.559 -0.763,-1.559 -0.728,-1.525 -0.727,-1.5
  lines w0.051: -0.537,-1.3 -0.537,1.3 2.063,1.3 2.063,-1.3 -0.537,-1.3
3D body "13lB-RF1-IPEX-SMD_BWIPX-1-001E.step": height 1.26, standoff 0, extent -0.79,-1.5 2.31,1.5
